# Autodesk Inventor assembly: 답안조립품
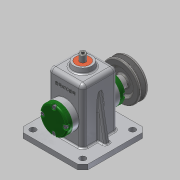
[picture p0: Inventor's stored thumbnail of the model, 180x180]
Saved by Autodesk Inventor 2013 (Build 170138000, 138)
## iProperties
Created: 2016-02
Part Number: 답안조립품
Document SubType Name: Assembly
Designer: dgall
Author: dgall
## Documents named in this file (16)
- C:\Users\dgall\Desktop\460211V1002\답안조립품.iam
- C:\Users\dgall\Desktop\460211V1002\본체.ipt
- C:\Users\dgall\Desktop\460211V1002\V벨트풀리.ipt
- C:\Users\dgall\Desktop\460211V1002\고정핀 1.2 x 10.ipt
- C:\Users\dgall\Desktop\460211V1002\뒤커버.ipt
- C:\Users\dgall\Desktop\460211V1002\링크.ipt
- C:\Users\dgall\Desktop\460211V1002\멈춤나사 M3x8.ipt
- C:\Users\dgall\Desktop\460211V1002\베어링 12 x 32 x 10.ipt
- C:\Users\dgall\Desktop\460211V1002\볼트 M4 x 12.ipt
- C:\Users\dgall\Desktop\460211V1002\부시.ipt
- C:\Users\dgall\Desktop\460211V1002\슬라이드.ipt
- C:\Users\dgall\Desktop\460211V1002\앞커버.ipt
- C:\Users\dgall\Desktop\460211V1002\오일실 12 25 7.ipt
- C:\Users\dgall\Desktop\460211V1002\키 4 x 4 x 10.ipt
- C:\Users\dgall\Desktop\460211V1002\편심축.ipt
- C:\Users\dgall\Desktop\460211V1002\핀 5 x 18.ipt
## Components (11 placed, 4 different names)
1. V벨트풀리:1
2. 고정핀 1.2 x 10:1 — 플러쉬:1
3. ISO 4762 M4 x 12:1
4. 핀 5 x 18:1 — 각도:1
5. ISO 4762 M4 x 12:2
6. ISO 4762 M4 x 12:3
7. ISO 4762 M4 x 12:4
8. ISO 4762 M4 x 12:5
9. ISO 4762 M4 x 12:6
10. ISO 4762 M4 x 12:7
11. ISO 4762 M4 x 12:8
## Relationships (2: Angle 1, Flush 1)
- 각도:1 [Angle]: 핀 5 x 18:1
- 플러쉬:1 [Flush]: 고정핀 1.2 x 10:1
